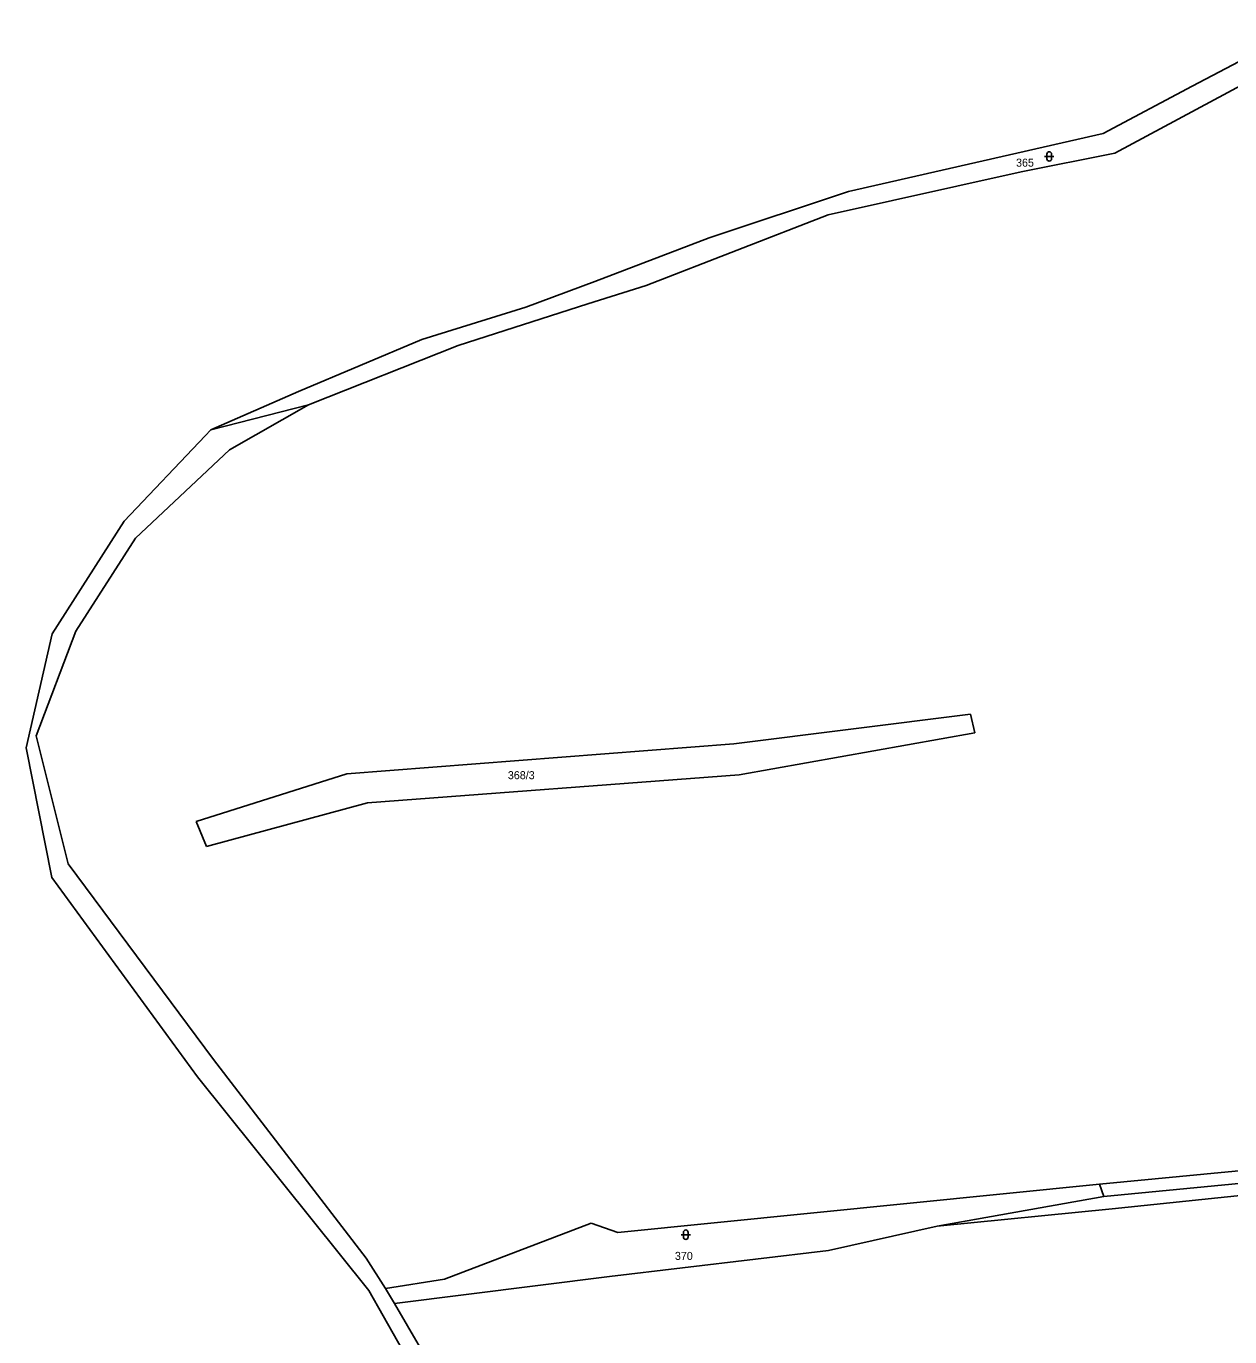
# Model space of a CAD drawing. Extents: x -754970 to -752637, y -970569 to -968179.
# Drawn here: x -754970.2 to -754714.7, y -968968.3 to -968689.9 of the extents above; entities that cross this region are included whole.
import ezdxf
from ezdxf.enums import TextEntityAlignment as Align

# ---------------------------------------------------------------- set-up
doc = ezdxf.new("R2010")
doc.units = 0
doc.header["$LTSCALE"] = 0.68
doc.layers.add('1', color=7, linetype='Continuous', lineweight=25)
doc.layers.add('3', color=7, linetype='Continuous', lineweight=25)
doc.layers.add('2', color=7, linetype='Continuous')

msp = doc.modelspace()

# ---------------------------------------------------------------- linework, layer by layer
at = {"layer": '1'}
for p, q in [((-754698.49, -968689.95), (-754722.7, -968702.69)), ((-754739.09, -968716.89), (-754695.67, -968693.59)), ((-754741.56, -968712.73), (-754722.7, -968702.69)), ((-754795.65, -968725.02), (-754741.56, -968712.73)), ((-754759.02, -968720.86), (-754739.09, -968716.89)), ((-754799.96, -968729.98), (-754759.02, -968720.86)), ((-754825.24, -968734.9), (-754795.65, -968725.02)), ((-754799.96, -968729.98), (-754838.64, -968745.02)), ((-754849.51, -968744.14), (-754825.24, -968734.9)), ((-754864.17, -968749.61), (-754849.51, -968744.14)), ((-754851.01, -968748.91), (-754838.64, -968745.02)), ((-754886.21, -968756.49), (-754864.17, -968749.61)), ((-754878.53, -968757.77), (-754851.01, -968748.91)), ((-754912.43, -968767.53), (-754886.21, -968756.49)), ((-754910.29, -968770.34), (-754878.53, -968757.77)), ((-754931.02, -968775.66), (-754912.43, -968767.53)), ((-754910.29, -968770.34), (-754931.02, -968775.66)), ((-754927.06, -968779.91), (-754910.29, -968770.34)), ((-754947.05, -968798.67), (-754927.06, -968779.91)), ((-754964.76, -968818.98), (-754949.45, -968795.07)), ((-754959.74, -968818.4), (-754947.05, -968798.67)), ((-754968.14, -968840.66), (-754959.74, -968818.4)), ((-754769.76, -968836.06), (-754820.03, -968842.35)), ((-754768.83, -968840.02), (-754769.76, -968836.06)), ((-754961.3, -968867.8), (-754968.14, -968840.66)), ((-754818.86, -968848.94), (-754768.83, -968840.02)), ((-754820.03, -968842.35), (-754902.17, -968848.75)), ((-754902.17, -968848.75), (-754934.14, -968858.81)), ((-754897.78, -968854.9), (-754818.86, -968848.94)), ((-754931.94, -968864.13), (-754897.78, -968854.9)), ((-754934.14, -968858.81), (-754931.94, -968864.13)), ((-754930.46, -968909.4), (-754961.3, -968867.8)), ((-754933.86, -968913.09), (-754964.78, -968870.74)), ((-754898.06, -968951.58), (-754930.46, -968909.4)), ((-754897.5, -968958.43), (-754933.86, -968913.09)), ((-754742.36, -968935.85), (-754669.15, -968928.87)), ((-754668.37, -968931.48), (-754741.45, -968938.5)), ((-754652.76, -968932.04), (-754739.66, -968941.09)), ((-754844.65, -968946.13), (-754742.36, -968935.85)), ((-754741.45, -968938.5), (-754742.36, -968935.85)), ((-754741.45, -968938.5), (-754776.79, -968944.76)), ((-754739.66, -968941.09), (-754776.79, -968944.76)), ((-754881.41, -968956.02), (-754850.28, -968944.16)), ((-754850.28, -968944.16), (-754844.65, -968946.13)), ((-754776.79, -968944.76), (-754799.9, -968949.95)), ((-754799.9, -968949.95), (-754846.41, -968955.44)), ((-754846.41, -968955.44), (-754892.08, -968961.21)), ((-754893.96, -968958.03), (-754881.41, -968956.02)), ((-754876.46, -968995.58), (-754897.5, -968958.43)), ((-754873.07, -968993.57), (-754892.08, -968961.21))]:
    msp.add_line(p, q, dxfattribs=at)
for points in [[(-754949.45, -968795.07), (-754932.22, -968776.92), (-754931.02, -968775.66)], [(-754964.78, -968870.74), (-754970.24, -968843.18), (-754964.76, -968818.98)], [(-754892.08, -968961.21), (-754893.96, -968958.03), (-754898.06, -968951.58)]]:
    msp.add_lwpolyline(points, dxfattribs=at)
at = {"layer": '3'}
for p, q in [((-754754.021, -968717.601), (-754752.019, -968717.601)), ((-754753.521, -968717.101), (-754753.521, -968718.102)), ((-754752.519, -968718.102), (-754752.519, -968717.101)), ((-754831.201, -968946.591), (-754829.199, -968946.591)), ((-754830.701, -968946.091), (-754830.701, -968947.092)), ((-754829.699, -968947.092), (-754829.699, -968946.091))]:
    msp.add_line(p, q, dxfattribs=at)
for centre, start, end in [((-754753.02, -968717.1009), 0, 180), ((-754753.02, -968718.1009), 180, 359.98789), ((-754830.2, -968946.0909), 0, 180), ((-754830.2, -968947.0909), 180, 359.98789)]:
    msp.add_arc(centre, 0.5, start, end, dxfattribs=at)

# ---------------------------------------------------------------- texts
at = {"layer": '2'}
for s, p in [('365', (-754758.179, -968719.775)), ('368/3', (-754865.13, -968849.855)), ('370', (-754830.609, -968951.945))]:
    msp.add_text(s, height=1.7, dxfattribs=at).set_placement(p, align=Align.CENTER)

doc.saveas('drawing.dxf')
